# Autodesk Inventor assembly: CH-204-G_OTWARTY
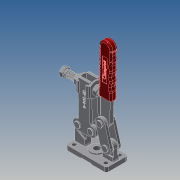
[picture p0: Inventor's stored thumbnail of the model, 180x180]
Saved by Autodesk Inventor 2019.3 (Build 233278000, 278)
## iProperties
Company: ·L?¤¤?
Created: 2010-06
Part Number: CH-204-G_OTWARTY
Material: Ogólny
Description: STEP AP203
Document SubType Name: Assembly
Designer: CADENGINEERING4
Sending System: SolidWorks 2005179
Preprocessor: SwSTEP 2.0
Title: CH-204-G.STEP
Author: ·L?¥Î?
Revision Number: ANY
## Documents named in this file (12)
- E:\STRONA\Horizontal toggle clamp\CH-204-G\CH-204-G_OTWARTY.iam
- E:\STRONA\Horizontal toggle clamp\CH-204-G\204-G-03___.ipt
- E:\STRONA\Horizontal toggle clamp\CH-204-G\M6___.ipt
- E:\STRONA\Horizontal toggle clamp\CH-204-G\CH-FC-12300-01___.ipt
- E:\STRONA\Horizontal toggle clamp\CH-204-G\204-G-02___.ipt
- E:\STRONA\Horizontal toggle clamp\CH-204-G\204-GB-06___.ipt
- E:\STRONA\Horizontal toggle clamp\CH-204-G\204-G-03___.iam
- E:\STRONA\Horizontal toggle clamp\CH-204-G\FW120(2)___.ipt
- E:\STRONA\Horizontal toggle clamp\CH-204-G\CH-FC-12130___.ipt
- E:\STRONA\Horizontal toggle clamp\CH-204-G\201-G-01___.ipt
- E:\STRONA\Horizontal toggle clamp\CH-204-G\204-G-04___.ipt
- E:\STRONA\Horizontal toggle clamp\CH-204-G\204-GB-04___.ipt
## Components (28 placed, 28 different names)
1. 204-G-03_??_1 — Zestawiające:45, Zestawiające:46, Zestawiające:47
2. M6_??_2 — Zestawiające:47, Zestawiające:48
3. CH-FC-12300-01_??_3 — Równoległe:3, Zestawiające:3, Zestawiające:7
4. 204-G-03_??_4 — Zestawiające:51, Zestawiające:52, Zestawiające:53
5. M6_??_5 — Zestawiające:32, Zestawiające:33
6. 204-G-02_??_6 — Zestawiające:34, Równoległe:5, Zestawiające:37, Zestawiające:38, Zestawiające:40
7. 204-GB-06_??_7 — Zestawiające:21, Zestawiające:22
8. 204-GB-06_??_8 — Zestawiające:11, Zestawiające:14, Zestawiające:17, Zestawiające:18
9. 204-GB-06_??_9 — Zestawiające:35, Zestawiające:37
10. 204-G-03_??_10 — Zestawiające:26, Zestawiające:27, Zestawiające:28
11. 204-G-03_??_11 [sub-assembly] — Zestawiające:24, Zestawiające:25, Zestawiające:49, Zestawiające:50, Kątowe:1
12. FW120(2)_??_13 — Równoległe:1, Równoległe:2, Zestawiające:4, Zestawiające:7, Zestawiające:8
13. FW120(2)_??_14 — Równoległe:2, Zestawiające:1, Zestawiające:5, Zestawiające:6
14. CH-FC-12130_??_15 — Równoległe:3, Zestawiające:1, Zestawiające:2, Zestawiające:3, Zestawiające:4, Zestawiające:9
15. 201-G-01_??_16 — Zestawiające:10, Równoległe:4, Zestawiające:11, Zestawiające:12, Zestawiające:34, Równoległe:5, Zestawiające:35, Zestawiające:36, Kątowe:1
16. 204-G-02_??_17 — Zestawiające:10, Równoległe:4, Zestawiające:13, Zestawiające:14, Zestawiające:16
17. 204-GB-06_??_18 — Zestawiające:41, Zestawiające:44
18. M6_??_19 — Zestawiające:28, Zestawiające:29
19. 204-GB-06_??_20 — Zestawiające:20, Zestawiające:23, Zestawiające:24
20. 204-GB-06_??_21 — Zestawiające:42, Zestawiające:43, Zestawiające:49
21. 204-G-04_??_22 — Równoległe:1, Zestawiające:5, Zestawiające:8, Zestawiające:9, Zestawiające:39, Zestawiające:40, Zestawiające:41, Zestawiające:42, Zestawiające:43, Zestawiające:44, Zestawiające:45, Zestawiające:46, Zestawiające:48, Zestawiające:50, Zestawiające:51, Zestawiające:52, Zestawiające:54
22. 204-GB-06_??_23 — Zestawiające:12, Zestawiające:13, Zestawiające:15
23. 204-GB-04_??_24 — Zestawiające:15, Zestawiające:16, Zestawiające:19, Zestawiające:20, Zestawiające:23, Zestawiające:25, Zestawiające:26, Zestawiające:27, Zestawiające:30, Zestawiające:31
24. 204-G-03_??_25 — Zestawiające:30, Zestawiające:31, Zestawiające:32
25. 204-GB-04_??_26 — Zestawiające:17, Zestawiające:18, Zestawiające:19, Zestawiające:21, Zestawiające:22, Zestawiające:29, Zestawiające:33
26. 204-GB-06_??_27 — Zestawiające:36, Zestawiające:38, Zestawiające:39
27. CH-FC-12300-01_??_28 — Zestawiające:2, Zestawiające:6
28. M6_??_29 — Zestawiające:53, Zestawiające:54
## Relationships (60: Mate 54, Flush 5, Angle 1)
- Równoległe:1 [Flush]: FW120(2)_??_13 ↔ 204-G-04_??_22
- Równoległe:2 [Flush]: FW120(2)_??_13 ↔ FW120(2)_??_14
- Równoległe:3 [Flush]: CH-FC-12300-01_??_3 ↔ CH-FC-12130_??_15
- Zestawiające:1 [Mate]: FW120(2)_??_14 ↔ CH-FC-12130_??_15
- Zestawiające:2 [Mate]: CH-FC-12130_??_15 ↔ CH-FC-12300-01_??_28
- Zestawiające:3 [Mate]: CH-FC-12300-01_??_3 ↔ CH-FC-12130_??_15
- Zestawiające:4 [Mate]: FW120(2)_??_13 ↔ CH-FC-12130_??_15
- Zestawiające:5 [Mate]: FW120(2)_??_14 ↔ 204-G-04_??_22
- Zestawiające:6 [Mate]: FW120(2)_??_14 ↔ CH-FC-12300-01_??_28
- Zestawiające:7 [Mate]: CH-FC-12300-01_??_3 ↔ FW120(2)_??_13
- Zestawiające:8 [Mate]: FW120(2)_??_13 ↔ 204-G-04_??_22
- Zestawiające:9 [Mate]: CH-FC-12130_??_15 ↔ 204-G-04_??_22
- Zestawiające:10 [Mate]: 201-G-01_??_16 ↔ 204-G-02_??_17
- Równoległe:4 [Flush]: 201-G-01_??_16 ↔ 204-G-02_??_17
- Zestawiające:11 [Mate]: 204-GB-06_??_8 ↔ 201-G-01_??_16
- Zestawiające:12 [Mate]: 201-G-01_??_16 ↔ 204-GB-06_??_23
- Zestawiające:13 [Mate]: 204-G-02_??_17 ↔ 204-GB-06_??_23
- Zestawiające:14 [Mate]: 204-GB-06_??_8 ↔ 204-G-02_??_17
- Zestawiające:15 [Mate]: 204-GB-06_??_23 ↔ 204-GB-04_??_24
- Zestawiające:16 [Mate]: 204-G-02_??_17 ↔ 204-GB-04_??_24
- Zestawiające:17 [Mate]: 204-GB-06_??_8 ↔ 204-GB-04_??_26
- Zestawiające:18 [Mate]: 204-GB-06_??_8 ↔ 204-GB-04_??_26
- Zestawiające:19 [Mate]: 204-GB-04_??_24 ↔ 204-GB-04_??_26
- Zestawiające:20 [Mate]: 204-GB-06_??_20 ↔ 204-GB-04_??_24
- Zestawiające:21 [Mate]: 204-GB-06_??_7 ↔ 204-GB-04_??_26
- Zestawiające:22 [Mate]: 204-GB-06_??_7 ↔ 204-GB-04_??_26
- Zestawiające:23 [Mate]: 204-GB-06_??_20 ↔ 204-GB-04_??_24
- Zestawiające:24 [Mate]: 204-G-03_??_11 ↔ 204-GB-06_??_20
- Zestawiające:25 [Mate]: 204-G-03_??_11 ↔ 204-GB-04_??_24
- Zestawiające:26 [Mate]: 204-G-03_??_10 ↔ 204-GB-04_??_24
- Zestawiające:27 [Mate]: 204-G-03_??_10 ↔ 204-GB-04_??_24
- Zestawiające:28 [Mate]: 204-G-03_??_10 ↔ M6_??_19
- Zestawiające:29 [Mate]: M6_??_19 ↔ 204-GB-04_??_26
- Zestawiające:30 [Mate]: 204-GB-04_??_24 ↔ 204-G-03_??_25
- Zestawiające:31 [Mate]: 204-GB-04_??_24 ↔ 204-G-03_??_25
- Zestawiające:32 [Mate]: M6_??_5 ↔ 204-G-03_??_25
- Zestawiające:33 [Mate]: M6_??_5 ↔ 204-GB-04_??_26
- Zestawiające:34 [Mate]: 204-G-02_??_6 ↔ 201-G-01_??_16
- Równoległe:5 [Flush]: 204-G-02_??_6 ↔ 201-G-01_??_16
- Zestawiające:35 [Mate]: 204-GB-06_??_9 ↔ 201-G-01_??_16
- Zestawiające:36 [Mate]: 201-G-01_??_16 ↔ 204-GB-06_??_27
- Zestawiające:37 [Mate]: 204-G-02_??_6 ↔ 204-GB-06_??_9
- Zestawiające:38 [Mate]: 204-G-02_??_6 ↔ 204-GB-06_??_27
- Zestawiające:39 [Mate]: 204-G-04_??_22 ↔ 204-GB-06_??_27
- Zestawiające:40 [Mate]: 204-G-02_??_6 ↔ 204-G-04_??_22
- Zestawiające:41 [Mate]: 204-GB-06_??_18 ↔ 204-G-04_??_22
- Zestawiające:42 [Mate]: 204-GB-06_??_21 ↔ 204-G-04_??_22
- Zestawiające:43 [Mate]: 204-GB-06_??_21 ↔ 204-G-04_??_22
- Zestawiające:44 [Mate]: 204-GB-06_??_18 ↔ 204-G-04_??_22
- Zestawiające:45 [Mate]: 204-G-03_??_1 ↔ 204-G-04_??_22
- Zestawiające:46 [Mate]: 204-G-03_??_1 ↔ 204-G-04_??_22
- Zestawiające:47 [Mate]: 204-G-03_??_1 ↔ M6_??_2
- Zestawiające:48 [Mate]: M6_??_2 ↔ 204-G-04_??_22
- Zestawiające:49 [Mate]: 204-G-03_??_11 ↔ 204-GB-06_??_21
- Zestawiające:50 [Mate]: 204-G-03_??_11 ↔ 204-G-04_??_22
- Zestawiające:51 [Mate]: 204-G-03_??_4 ↔ 204-G-04_??_22
- Zestawiające:52 [Mate]: 204-G-03_??_4 ↔ 204-G-04_??_22
- Zestawiające:53 [Mate]: 204-G-03_??_4 ↔ M6_??_29
- Zestawiające:54 [Mate]: 204-G-04_??_22 ↔ M6_??_29
- Kątowe:1 [Angle]: 204-G-03_??_11 ↔ 201-G-01_??_16
